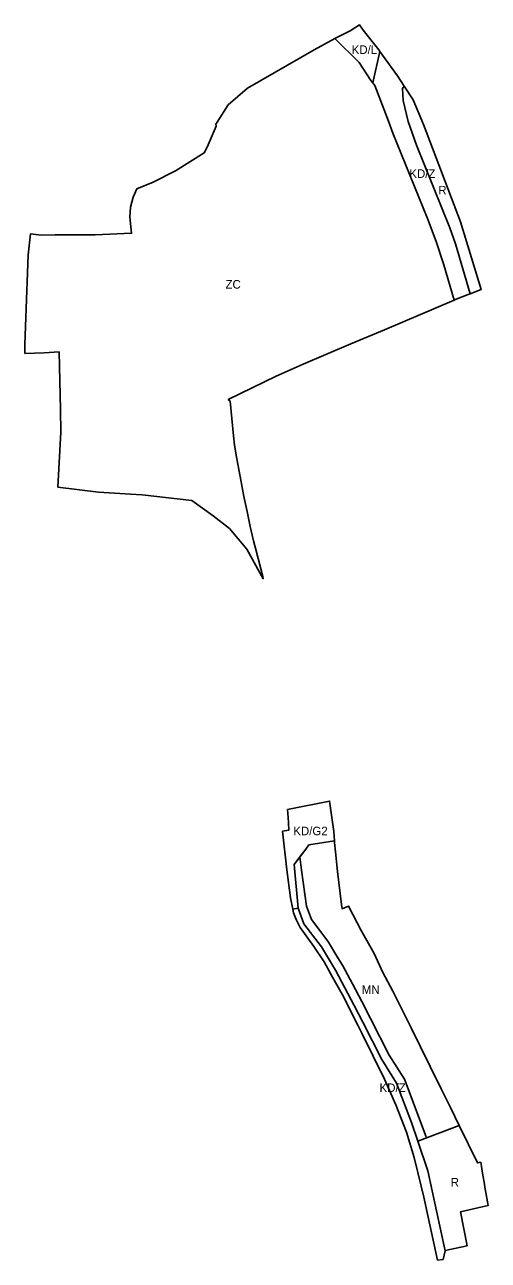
# Model space of a CAD drawing. Extents: x 7436680 to 7439366, y 5548361 to 5550775.
# Drawn here: x 7438826 to 7439366, y 5548753 to 5550194 of the extents above; entities that cross this region are included whole.
import ezdxf

# ---------------------------------------------------------------- set-up
doc = ezdxf.new("R2010")
doc.units = 0
for name, color, linetype in [('linie_rozgraniczajace', 7, 'Continuous'), ('linie_zabudowy_nieprzekraczalne', 7, 'Continuous'), ('oznaczenia_przeznaczen', 7, 'Continuous')]:
    doc.layers.add(name, color=color, linetype=linetype)

msp = doc.modelspace()

# ---------------------------------------------------------------- linework, layer by layer
at = {"layer": 'linie_rozgraniczajace'}
for p, q in [((7439153.4, 5549233.1), (7439157.2, 5549237.9)), ((7439144.6, 5549164.2), (7439140.1, 5549214.9)), ((7439138.3, 5549162.9), (7439144.6, 5549164.2))]:
    msp.add_line(p, q, dxfattribs=at)
for points in [[(7439187.5, 5550178.1), (7439205.1, 5550187), (7439216.1, 5550194.3), (7439220.4, 5550188), (7439238.6, 5550164.9), (7439240, 5550163), (7439231.7, 5550126.4), (7439229.4, 5550129.4), (7439215.6, 5550150.4)], [(7438825.8, 5549811.1), (7438826.1, 5549821.4), (7438827, 5549852.7), (7438830, 5549925.8), (7438832.7, 5549950.5), (7438845, 5549948.9), (7438861.4, 5549949.3), (7438878.8, 5549949.1), (7438893.2, 5549949.1), (7438908.1, 5549949.2), (7438950.4, 5549951.2), (7438948.5, 5549969.8), (7438949.1, 5549981.6), (7438952.2, 5549993.1), (7438956.5, 5550003.1), (7438975.5, 5550010.9), (7439001.8, 5550023.9), (7439018.3, 5550034.6), (7439035.2, 5550044.9), (7439038.4, 5550051.5), (7439049, 5550075.9), (7439048.6, 5550078.2), (7439050.2, 5550080.7), (7439063, 5550100.7), (7439085.5, 5550120.2), (7439163.3, 5550165), (7439187.5, 5550178.1), (7439215.6, 5550150.4), (7439229.4, 5550129.4), (7439231.7, 5550126.4), (7439234, 5550123.3), (7439250, 5550081.8), (7439255, 5550067.9), (7439295.4, 5549968.4), (7439305.5, 5549941.5), (7439314.3, 5549914.3), (7439326.5, 5549873), (7439245.3, 5549838.4), (7439206.2, 5549822), (7439150.4, 5549798.4), (7439118.8, 5549784.3), (7439063.2, 5549757.4), (7439065.4, 5549755.2), (7439069.3, 5549714.8), (7439070.3, 5549703.9), (7439073.2, 5549688), (7439078, 5549661.4), (7439081.2, 5549644), (7439085, 5549626.6), (7439088.8, 5549609.2), (7439092.4, 5549592.5), (7439095.1, 5549582.2), (7439103.4, 5549550.7), (7439103.9, 5549548.3), (7439084.8, 5549582.9), (7439064.4, 5549606.9), (7439045.4, 5549621.7), (7439020.8, 5549639.5), (7438962.7, 5549646.1), (7438949, 5549647), (7438912, 5549649.4), (7438864.5, 5549655.2), (7438867.8, 5549719.1), (7438867.5, 5549745.7), (7438866.7, 5549779.2), (7438865.9, 5549812.7), (7438848.5, 5549811.8)], [(7439231.7, 5550126.4), (7439240, 5550163), (7439260.3, 5550134.9), (7439268.1, 5550122.7), (7439266.2, 5550119.9), (7439267.1, 5550105.9), (7439273, 5550081.5), (7439282.4, 5550053.7), (7439321.3, 5549957.6), (7439327.9, 5549938.8), (7439345.1, 5549880.6), (7439342.7, 5549879.7), (7439329, 5549874.1), (7439326.5, 5549873), (7439314.3, 5549914.3), (7439305.5, 5549941.5), (7439295.4, 5549968.4), (7439255, 5550067.9), (7439250, 5550081.8), (7439234, 5550123.3)], [(7439266.2, 5550119.9), (7439268.1, 5550122.7), (7439278.6, 5550106.6), (7439290.9, 5550078.1), (7439333.8, 5549964.6), (7439357.8, 5549885.5), (7439345.1, 5549880.6), (7439327.9, 5549938.8), (7439321.3, 5549957.6), (7439282.4, 5550053.7), (7439273, 5550081.5), (7439267.1, 5550105.9)], [(7439140.1, 5549214.9), (7439153.4, 5549233.1), (7439157.2, 5549237.9), (7439186.9, 5549242.8), (7439187.1, 5549240.6), (7439188, 5549229.9), (7439190.6, 5549207), (7439195.3, 5549168.5), (7439195.9, 5549163.5), (7439203.3, 5549166.5), (7439218.1, 5549138.2), (7439233.1, 5549111.3), (7439243.4, 5549089), (7439254.8, 5549067.2), (7439265.8, 5549045.4), (7439276.5, 5549024.4), (7439287.4, 5549002.4), (7439298.6, 5548979.5), (7439311.3, 5548953.5), (7439322.1, 5548931.5), (7439332.2, 5548910.7), (7439284.2, 5548892.4), (7439276.8, 5548914.2), (7439259.4, 5548960.1), (7439242, 5548987.8), (7439220.1, 5549031), (7439210, 5549050.7), (7439199.2, 5549071.2), (7439188.1, 5549092), (7439171.8, 5549119), (7439151.3, 5549146), (7439144.6, 5549164.2)], [(7439284.2, 5548892.4), (7439332.2, 5548910.7), (7439353.6, 5548867.1), (7439357.5, 5548867.9), (7439359.7, 5548855.1), (7439361.8, 5548842.4), (7439362.4, 5548838.6), (7439366.2, 5548817.4), (7439359.2, 5548815.8), (7439333.7, 5548809.9), (7439341.5, 5548770.5), (7439316, 5548765), (7439315.9, 5548764.7), (7439295.7, 5548858)]]:
    msp.add_lwpolyline(points, close=True, dxfattribs=at)
for points in [[(7439157.2, 5549237.9), (7439186.9, 5549242.8), (7439186.1, 5549253.4), (7439181.3, 5549288.9), (7439132.2, 5549279.3)], [(7439132.2, 5549279.3), (7439133, 5549270), (7439133.4, 5549263.8), (7439133.9, 5549255.2), (7439126.2, 5549253.8)], [(7439126.2, 5549253.8), (7439131.6, 5549208.7), (7439135.6, 5549176.1), (7439138.3, 5549162.9)], [(7439140.1, 5549214.9), (7439146.6, 5549223.8), (7439153.4, 5549233.1)], [(7439307.2, 5548753.5), (7439313.5, 5548754.5), (7439315.9, 5548764.7), (7439295.7, 5548858), (7439284.2, 5548892.4), (7439276.8, 5548914.2), (7439259.4, 5548960.1), (7439242, 5548987.8), (7439220.1, 5549031), (7439210, 5549050.7), (7439199.2, 5549071.2), (7439188.1, 5549092), (7439171.8, 5549119), (7439151.3, 5549146), (7439144.6, 5549164.2), (7439138.3, 5549162.9)], [(7439138.3, 5549162.9), (7439139.2, 5549158.8), (7439142.2, 5549150.7), (7439147.1, 5549141.7), (7439162.9, 5549119.4), (7439174.8, 5549101.4), (7439184.7, 5549083.7), (7439196.3, 5549062.9), (7439214.2, 5549027.6), (7439218.9, 5549018.4), (7439245.2, 5548964.8), (7439258.4, 5548934.9), (7439270.8, 5548903), (7439279.8, 5548873.5), (7439288, 5548840), (7439291.2, 5548827.1), (7439307.2, 5548753.5)]]:
    msp.add_lwpolyline(points, dxfattribs=at)
at = {"layer": 'linie_zabudowy_nieprzekraczalne'}
msp.add_lwpolyline([(7439146.6, 5549223.8), (7439148.6, 5549208.4), (7439154.4, 5549166.4), (7439160.2, 5549150.8), (7439175.9, 5549130.2), (7439180.1, 5549124.6), (7439189.8, 5549108), (7439196.8, 5549096.9), (7439208, 5549075.9), (7439218.8, 5549055.4), (7439229, 5549035.5), (7439250.7, 5548992.8), (7439268.4, 5548964.6), (7439294, 5548897.3)], dxfattribs=at)

# ---------------------------------------------------------------- texts
at = {"layer": 'oznaczenia_przeznaczen'}
for s, p in [('KD/L', (7439207, 5550160.2)), ('KD/Z', (7439274.2, 5550015.7)), ('R', (7439308, 5549996.4)), ('ZC', (7439059.9, 5549886.6)), ('KD/G2', (7439138.9, 5549249.1)), ('MN', (7439218.8, 5549064.2)), ('KD/Z', (7439239.5, 5548949.7)), ('R', (7439322.4, 5548839.5))]:
    msp.add_text(s, height=10, dxfattribs=at).set_placement(p)

doc.saveas('drawing.dxf')
